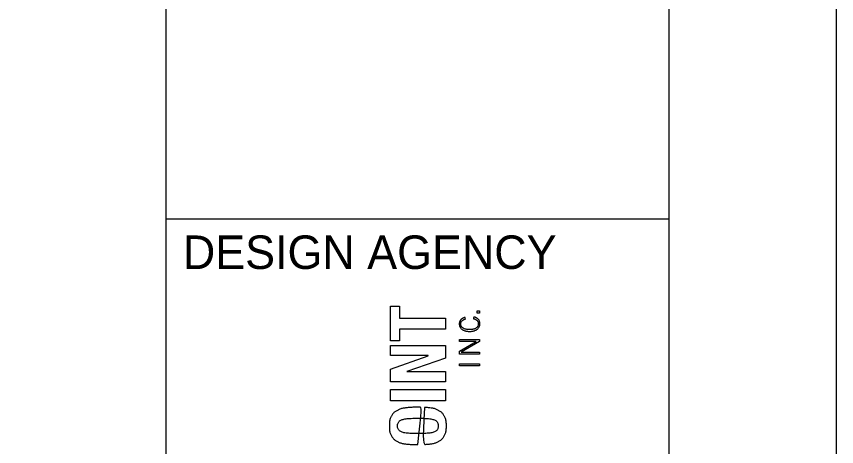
# Model space of a CAD drawing. Extents: x 208586767.6 to 208586821.4, y -134301046.9 to -134301022.9.
# Drawn here: x 208586807.482 to 208586809.928, y -134301041.121 to -134301039.837 of the extents above; entities that cross this region are included whole.
import ezdxf

# ---------------------------------------------------------------- set-up
doc = ezdxf.new("R2010")
doc.units = 0
for name, color, linetype in [('SH_Border', 7, 'Continuous'), ('SH_Cut_Line', 7, 'Continuous'), ('SH_Data', 7, 'Continuous')]:
    doc.layers.add(name, color=color, linetype=linetype)

msp = doc.modelspace()

# ---------------------------------------------------------------- linework, layer by layer
at = {"layer": 'SH_Border'}
for p, q in [((208586807.9283, -134301044.4407), (208586807.9283, -134301023.4407)), ((208586807.9283, -134301040.4407), (208586809.4283, -134301040.4407))]:
    msp.add_line(p, q, dxfattribs=at)
msp.add_lwpolyline([(208586777.4283, -134301023.4407), (208586809.4283, -134301023.4407), (208586809.4283, -134301044.4407), (208586777.4283, -134301044.4407)], close=True, dxfattribs=at)
at = {"layer": 'SH_Cut_Line'}
msp.add_lwpolyline([(208586775.9283, -134301044.9407), (208586809.9283, -134301044.9407), (208586809.9283, -134301022.9407), (208586775.9283, -134301022.9407)], close=True, dxfattribs=at)
at = {"layer": 'SH_Data'}
for points in [[(208586808.5978, -134301040.7014), (208586808.6249, -134301040.7014), (208586808.6249, -134301040.7371), (208586808.7612, -134301040.7371), (208586808.7612, -134301040.7699), (208586808.6249, -134301040.7699), (208586808.6249, -134301040.8057), (208586808.5978, -134301040.8057), (208586808.5978, -134301040.7014)], [(208586808.8632, -134301040.7228), (208586808.8558, -134301040.7228), (208586808.8558, -134301040.7157), (208586808.8632, -134301040.7157), (208586808.8632, -134301040.7228)], [(208586808.8037, -134301040.8447), (208586808.8037, -134301040.8356), (208586808.8533, -134301040.8072), (208586808.8533, -134301040.807), (208586808.8037, -134301040.807), (208586808.8037, -134301040.8016), (208586808.8632, -134301040.8016), (208586808.8632, -134301040.8072), (208586808.8081, -134301040.8391), (208586808.8081, -134301040.8393), (208586808.8632, -134301040.8393), (208586808.8632, -134301040.8447), (208586808.8037, -134301040.8447)], [(208586808.5978, -134301040.8894), (208586808.7097, -134301040.8496), (208586808.7097, -134301040.8491), (208586808.5978, -134301040.8491), (208586808.5978, -134301040.819), (208586808.7612, -134301040.819), (208586808.7612, -134301040.8565), (208586808.6468, -134301040.8968), (208586808.6468, -134301040.8972), (208586808.7612, -134301040.8972), (208586808.7612, -134301040.9274), (208586808.5978, -134301040.9274), (208586808.5978, -134301040.8894)], [(208586808.8037, -134301040.8794), (208586808.8037, -134301040.874), (208586808.8632, -134301040.874), (208586808.8632, -134301040.8794), (208586808.8037, -134301040.8794)], [(208586808.7612, -134301040.9838), (208586808.5978, -134301040.9838), (208586808.5978, -134301040.9509), (208586808.7612, -134301040.9509), (208586808.7612, -134301040.9838)]]:
    msp.add_lwpolyline(points, dxfattribs=at)
for points in [[(208586808.8211, -134301040.7402), (208586808.8168, -134301040.7415), (208586808.8134, -134301040.7433), (208586808.811, -134301040.7457), (208586808.8086, -134301040.7481), (208586808.8074, -134301040.7511), (208586808.8074, -134301040.7547), (208586808.8074, -134301040.7577), (208586808.8081, -134301040.7602), (208586808.8094, -134301040.7623), (208586808.8107, -134301040.7644), (208586808.8126, -134301040.7662), (208586808.815, -134301040.7676), (208586808.8173, -134301040.769), (208586808.8201, -134301040.77), (208586808.8233, -134301040.7707), (208586808.8265, -134301040.7714), (208586808.8299, -134301040.7717), (208586808.8335, -134301040.7717), (208586808.8371, -134301040.7717), (208586808.8405, -134301040.7714), (208586808.8437, -134301040.7707), (208586808.8469, -134301040.77), (208586808.8496, -134301040.769), (208586808.852, -134301040.7676), (208586808.8544, -134301040.7661), (208586808.8562, -134301040.7643), (208586808.8576, -134301040.7621), (208586808.8589, -134301040.7599), (208586808.8596, -134301040.7572), (208586808.8596, -134301040.7541), (208586808.8596, -134301040.7518), (208586808.8592, -134301040.7497), (208586808.8584, -134301040.7481), (208586808.8576, -134301040.7464), (208586808.8565, -134301040.745), (208586808.8552, -134301040.7438), (208586808.8539, -134301040.7427), (208586808.8523, -134301040.7417), (208586808.8506, -134301040.741), (208586808.8488, -134301040.7402), (208586808.847, -134301040.7396), (208586808.8451, -134301040.7391), (208586808.8451, -134301040.7391), (208586808.846, -134301040.734), (208586808.846, -134301040.734), (208586808.8486, -134301040.7346), (208586808.851, -134301040.7353), (208586808.8533, -134301040.7364), (208586808.8555, -134301040.7374), (208586808.8574, -134301040.7387), (208586808.859, -134301040.7403), (208586808.8606, -134301040.7419), (208586808.8618, -134301040.7438), (208586808.8627, -134301040.7461), (208586808.8636, -134301040.7484), (208586808.8641, -134301040.7511), (208586808.8641, -134301040.7542), (208586808.8641, -134301040.7578), (208586808.8633, -134301040.7611), (208586808.8619, -134301040.7639), (208586808.8604, -134301040.7667), (208586808.8583, -134301040.7691), (208586808.8556, -134301040.7711), (208586808.853, -134301040.773), (208586808.8497, -134301040.7745), (208586808.846, -134301040.7756), (208586808.8423, -134301040.7766), (208586808.8381, -134301040.7771), (208586808.8335, -134301040.7771), (208586808.8289, -134301040.7771), (208586808.8247, -134301040.7766), (208586808.8209, -134301040.7756), (208586808.8172, -134301040.7745), (208586808.814, -134301040.773), (208586808.8113, -134301040.7711), (208586808.8086, -134301040.7691), (208586808.8065, -134301040.7667), (208586808.8051, -134301040.7639), (208586808.8036, -134301040.7611), (208586808.8029, -134301040.7578), (208586808.8029, -134301040.7542), (208586808.8029, -134301040.7516), (208586808.8033, -134301040.7492), (208586808.8042, -134301040.7471), (208586808.8051, -134301040.745), (208586808.8063, -134301040.7432), (208586808.8078, -134301040.7416), (208586808.8094, -134301040.7401), (208586808.8112, -134301040.7388), (208586808.8133, -134301040.7377), (208586808.8154, -134301040.7367), (208586808.8177, -134301040.7358), (208586808.8201, -134301040.7352), (208586808.8201, -134301040.7352), (208586808.8211, -134301040.7402), (208586808.8211, -134301040.7402)], [(208586808.6793, -134301041.1149), (208586808.667, -134301041.1149), (208586808.6556, -134301041.1143), (208586808.6451, -134301041.1132), (208586808.6347, -134301041.1121), (208586808.6257, -134301041.1095), (208586808.6182, -134301041.1056), (208586808.6107, -134301041.1017), (208586808.6049, -134301041.0961), (208586808.6007, -134301041.0888), (208586808.5965, -134301041.0814), (208586808.5944, -134301041.0716), (208586808.5944, -134301041.0592), (208586808.5944, -134301041.0468), (208586808.5965, -134301041.0369), (208586808.6007, -134301041.0296), (208586808.6049, -134301041.0223), (208586808.6107, -134301041.0167), (208586808.6182, -134301041.0128), (208586808.6257, -134301041.0088), (208586808.6347, -134301041.0063), (208586808.6451, -134301041.0052), (208586808.6556, -134301041.004), (208586808.667, -134301041.0035), (208586808.6793, -134301041.0035), (208586808.6861, -134301041.0035), (208586808.6926, -134301041.0036), (208586808.6988, -134301041.004)], [(208586808.6988, -134301041.004), (208586808.7039, -134301041.0043), (208586808.7088, -134301041.0047), (208586808.7135, -134301041.0052), (208586808.724, -134301041.0063), (208586808.733, -134301041.0088), (208586808.7404, -134301041.0128), (208586808.7479, -134301041.0167), (208586808.7538, -134301041.0223), (208586808.758, -134301041.0296), (208586808.7622, -134301041.0369), (208586808.7643, -134301041.0468), (208586808.7643, -134301041.0592), (208586808.7643, -134301041.0716), (208586808.7622, -134301041.0814), (208586808.758, -134301041.0888), (208586808.7538, -134301041.0961), (208586808.7479, -134301041.1017), (208586808.7404, -134301041.1056), (208586808.733, -134301041.1095), (208586808.724, -134301041.1121), (208586808.7135, -134301041.1132), (208586808.7031, -134301041.1143), (208586808.6917, -134301041.1149), (208586808.6793, -134301041.1149)], [(208586808.6793, -134301041.0821), (208586808.6903, -134301041.0821), (208586808.6996, -134301041.0818), (208586808.7073, -134301041.0813), (208586808.715, -134301041.0807), (208586808.7212, -134301041.0797), (208586808.726, -134301041.078), (208586808.7308, -134301041.0764), (208586808.7343, -134301041.0741), (208586808.7365, -134301041.0711), (208586808.7387, -134301041.0681), (208586808.7398, -134301041.0641), (208586808.7398, -134301041.0592), (208586808.7398, -134301041.0543), (208586808.7387, -134301041.0503), (208586808.7365, -134301041.0473), (208586808.7343, -134301041.0443), (208586808.7308, -134301041.042), (208586808.726, -134301041.0403), (208586808.7212, -134301041.0387), (208586808.715, -134301041.0376), (208586808.7073, -134301041.0371), (208586808.6996, -134301041.0366), (208586808.6903, -134301041.0363), (208586808.6793, -134301041.0363), (208586808.6684, -134301041.0363), (208586808.6591, -134301041.0366), (208586808.6515, -134301041.0371), (208586808.6439, -134301041.0376), (208586808.6376, -134301041.0387), (208586808.6328, -134301041.0403), (208586808.6279, -134301041.042), (208586808.6243, -134301041.0443), (208586808.6221, -134301041.0473), (208586808.6199, -134301041.0503), (208586808.6188, -134301041.0543), (208586808.6188, -134301041.0592), (208586808.6188, -134301041.0641), (208586808.6199, -134301041.0681), (208586808.6221, -134301041.0711), (208586808.6243, -134301041.0741), (208586808.6279, -134301041.0764), (208586808.6328, -134301041.078), (208586808.6376, -134301041.0797), (208586808.6439, -134301041.0807), (208586808.6515, -134301041.0813), (208586808.6591, -134301041.0818), (208586808.6684, -134301041.0821), (208586808.6793, -134301041.0821)]]:
    msp.add_open_spline(points, degree=3, dxfattribs=at)

# ---------------------------------------------------------------- texts
msp.add_text('DESIGN AGENCY', height=0.1, dxfattribs=at).set_placement((208586807.9783, -134301040.5907))

doc.saveas('drawing.dxf')
